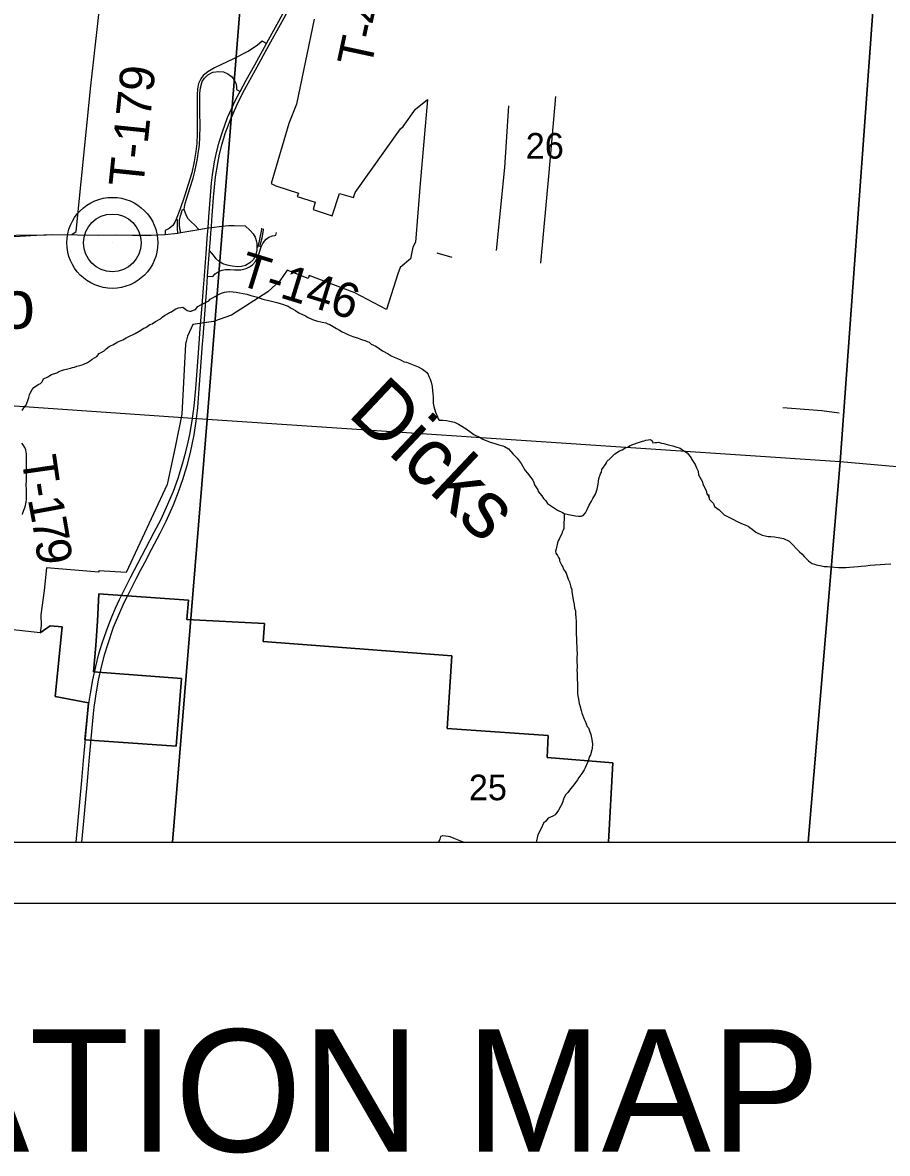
# Model space of a CAD drawing. Extents: x 0 to 34, y 0 to 22.
# Drawn here: x 5.086 to 6.5, y 13.589 to 15.439 of the extents above; entities that cross this region are included whole.
import ezdxf

# ---------------------------------------------------------------- set-up
doc = ezdxf.new("R2010")
doc.units = 0
for name, color, linetype in [('GM_X_City_Street', 7, 'Continuous'), ('GM_X_Corporation', 7, 'Continuous'), ('GM_X_Interchange_Ramps', 7, 'Continuous'), ('GM_X_Minor_River', 7, 'Continuous'), ('GM_X_Minor_River_Text', 7, 'Continuous'), ('GM_X_Rail_Line', 7, 'Continuous'), ('GM_X_Section_Text', 7, 'Continuous'), ('GM_X_State_Route', 7, 'Continuous'), ('GM_X_Township_Road', 7, 'Continuous'), ('GM_X_Township_Road_Text', 7, 'Continuous'), ('GM_X_Unincorporated', 7, 'Continuous'), ('GM_X_Unincorporated_Location', 7, 'Continuous'), ('GM_X_Unincorporated_Text', 7, 'Continuous'), ('SH_Data', 7, 'Continuous'), ('SH_Text', 7, 'Continuous')]:
    doc.layers.add(name, color=color, linetype=linetype)

msp = doc.modelspace()

# ---------------------------------------------------------------- linework, layer by layer
at = {"layer": 'GM_X_City_Street'}
msp.add_line((5.7638, 15.062), (5.7881, 15.055), dxfattribs=at)
for points in [[(5.9336, 15.0452), (5.9473, 15.1933), (5.9583, 15.3179)], [(5.8613, 15.0658), (5.8746, 15.2014), (5.8811, 15.3027)]]:
    msp.add_lwpolyline(points, dxfattribs=at)
at = {"layer": 'GM_X_Corporation'}
for points in [[(2.1, 20.898), (2.1, 14.098), (8.9, 14.098), (8.9, 19.3874)], [(5.5629, 15.4444), (5.5342, 15.3055), (5.5216, 15.2734), (5.4924, 15.1754), (5.5001, 15.1717), (5.5373, 15.1599), (5.5354, 15.1543), (5.5648, 15.1447), (5.5614, 15.1329), (5.5925, 15.1228), (5.6042, 15.1593), (5.6273, 15.1524), (5.63, 15.1609), (5.704, 15.2649), (5.7085, 15.2686), (5.7287, 15.2969), (5.7486, 15.3127), (5.7362, 15.1753), (5.7289, 15.0793), (5.7244, 15.0711), (5.7207, 15.0525), (5.7035, 15.0383), (5.7, 15.0279), (5.6811, 14.9695), (5.6294, 14.9969), (5.555, 15.0252), (5.5534, 15.0203), (5.5189, 15.0335), (5.5066, 15.0163), (5.4871, 14.9982), (5.428, 14.9599), (5.3983, 14.9495), (5.3648, 14.9446), (5.3558, 14.9259), (5.3539, 14.9171), (5.3531, 14.9153), (5.3527, 14.9128), (5.3467, 14.7981), (5.336, 14.7471), (5.3225, 14.6832), (5.2557, 14.5389), (5.2109, 14.5419), (5.211, 14.5395), (5.1255, 14.5467), (5.1215, 14.5095), (5.1158, 14.4697), (5.1168, 14.4526), (5.1151, 14.4405), (5.1314, 14.4521), (5.1509, 14.4503), (5.1394, 14.3361), (5.1941, 14.326), (5.1914, 14.2971), (5.1881, 14.2652), (5.3373, 14.2548), (5.3461, 14.3655), (5.2019, 14.3766), (5.2057, 14.4196), (5.2089, 14.4593), (5.211, 14.5041), (5.3573, 14.4941), (5.3549, 14.4625), (5.4815, 14.4556), (5.4798, 14.4262), (5.7879, 14.4031), (5.7803, 14.2842), (5.9457, 14.2723), (5.944, 14.2365), (6.0516, 14.228), (6.0442, 14.098), (8.9, 14.098)], [(4.8185, 14.098), (5.3312, 14.098), (5.3881, 14.7897), (4.6238, 14.8425)], [(4.828, 14.098), (6.0442, 14.098), (6.0516, 14.228), (5.944, 14.2365), (5.9457, 14.2723), (5.7803, 14.2842), (5.7879, 14.4031), (5.4798, 14.4262), (5.4815, 14.4556), (5.3549, 14.4625), (5.3573, 14.4941), (5.211, 14.5041), (5.2089, 14.4593), (5.2057, 14.4196), (5.2019, 14.3766), (5.3461, 14.3655), (5.3373, 14.2548), (5.1881, 14.2652), (5.1914, 14.2971), (5.1941, 14.326), (5.1394, 14.3361), (5.1509, 14.4503), (5.1314, 14.4521), (5.1151, 14.4405), (4.8868, 14.4655)]]:
    msp.add_lwpolyline(points, dxfattribs=at)
for points in [[(4.4791, 15.9012), (5.4696, 15.8133), (5.3881, 14.7897), (4.6238, 14.8425), (4.6032, 14.8565), (4.5856, 14.8637), (4.5735, 14.8663), (4.5679, 14.8668), (4.5637, 14.865), (4.5556, 14.8606), (4.5464, 14.8574), (4.5354, 14.8542), (4.5274, 14.851), (4.4054, 15.0286)], [(5.4696, 15.8133), (6.4956, 15.7207), (6.423, 14.72), (5.3881, 14.7897)], [(6.4956, 15.7207), (7.5243, 15.6293), (7.4312, 14.6313), (6.423, 14.72)], [(5.3312, 14.098), (6.3708, 14.098), (6.423, 14.72), (5.3881, 14.7897)], [(6.3708, 14.098), (7.3908, 14.098), (7.4312, 14.6313), (6.423, 14.72)]]:
    msp.add_lwpolyline(points, close=True, dxfattribs=at)
at = {"layer": 'GM_X_Interchange_Ramps'}
for points in [[(5.485, 15.4047), (5.4781, 15.4086), (5.4699, 15.4015), (5.4555, 15.3918), (5.4312, 15.3793), (5.3998, 15.3646), (5.3889, 15.3581), (5.3817, 15.3521), (5.3776, 15.3468), (5.3741, 15.3393), (5.3722, 15.3304), (5.3718, 15.3204), (5.3719, 15.2903), (5.3718, 15.2571), (5.371, 15.2408), (5.3694, 15.228), (5.3668, 15.2113), (5.3627, 15.1929), (5.3508, 15.1547), (5.3432, 15.1326), (5.3372, 15.1169), (5.3351, 15.1123), (5.3317, 15.107), (5.326, 15.1021), (5.3195, 15.0985), (5.3193, 15.092)], [(5.3743, 15.1001), (5.3675, 15.1077), (5.3625, 15.1121), (5.3569, 15.1177), (5.3542, 15.1226), (5.3518, 15.1284), (5.3503, 15.1329), (5.351, 15.1371), (5.3522, 15.1428), (5.3542, 15.1496), (5.3602, 15.1687), (5.365, 15.1841), (5.3678, 15.1953), (5.3702, 15.2055), (5.3721, 15.2163), (5.374, 15.2283), (5.3752, 15.2379), (5.3761, 15.2517), (5.3765, 15.2682), (5.3761, 15.2945), (5.3762, 15.3228), (5.3771, 15.3321), (5.38, 15.3421), (5.3837, 15.348), (5.3892, 15.3534), (5.3974, 15.3578), (5.4063, 15.3588), (5.4149, 15.3579), (5.4217, 15.3548), (5.4277, 15.3504), (5.4322, 15.3451), (5.4347, 15.3397), (5.4358, 15.3342), (5.4361, 15.3295), (5.4419, 15.3262)], [(5.3452, 15.0954), (5.3432, 15.1011), (5.3429, 15.1083), (5.3429, 15.1154), (5.3443, 15.1227), (5.3475, 15.1327), (5.3503, 15.1329)], [(5.3372, 15.1169), (5.3388, 15.1164), (5.3391, 15.102), (5.3393, 15.0945)], [(5.3888, 15.0239), (5.3972, 15.0233), (5.4013, 15.0277), (5.4076, 15.032), (5.4128, 15.0338), (5.418, 15.0347), (5.4254, 15.0348), (5.4327, 15.0345), (5.4433, 15.0344), (5.4519, 15.0365), (5.4575, 15.0392), (5.4619, 15.0427), (5.467, 15.048), (5.4706, 15.0542), (5.4731, 15.0616), (5.4761, 15.0719), (5.4788, 15.0772), (5.4811, 15.0808), (5.4845, 15.0843), (5.489, 15.0875), (5.4946, 15.0897), (5.498, 15.0906), (5.5001, 15.091), (5.5016, 15.0955)], [(5.4766, 15.1025), (5.4766, 15.1005), (5.4707, 15.0713), (5.4695, 15.0712)], [(5.4761, 15.0719), (5.4744, 15.0723), (5.4778, 15.0865), (5.4802, 15.0994), (5.4803, 15.1014)]]:
    msp.add_lwpolyline(points, dxfattribs=at)
at = {"layer": 'GM_X_Minor_River'}
for points in [[(5.1601, 14.8723), (5.1643, 14.8732), (5.1678, 14.8743), (5.1708, 14.8753), (5.1747, 14.8767), (5.1797, 14.878), (5.1835, 14.879), (5.1862, 14.88), (5.1924, 14.8829), (5.1971, 14.8857), (5.1999, 14.8879), (5.2077, 14.8926), (5.2116, 14.8974), (5.2144, 14.8992), (5.2198, 14.902), (5.2226, 14.905), (5.2277, 14.9086), (5.2308, 14.9107), (5.2339, 14.9118), (5.2417, 14.9164), (5.2448, 14.9175), (5.2502, 14.9195), (5.2556, 14.9228), (5.263, 14.9267), (5.2657, 14.9277), (5.27, 14.9302), (5.277, 14.9342), (5.2844, 14.9388), (5.2875, 14.9402), (5.2945, 14.9446), (5.298, 14.9459), (5.3034, 14.9496), (5.3116, 14.9542), (5.3144, 14.9568), (5.3183, 14.9593), (5.3233, 14.9625), (5.3264, 14.9643), (5.3299, 14.9657), (5.3342, 14.969), (5.337, 14.9704), (5.3412, 14.9721), (5.3447, 14.9728), (5.3481, 14.973), (5.3525, 14.9698), (5.3551, 14.9678), (5.3589, 14.9665), (5.3616, 14.9668), (5.3658, 14.9682), (5.3689, 14.9696), (5.3725, 14.9744), (5.3776, 14.9769), (5.3873, 14.9819), (5.3907, 14.9833), (5.3931, 14.9862), (5.4009, 14.9905), (5.406, 14.9937), (5.413, 14.9969), (5.4164, 14.9979), (5.4202, 14.9985), (5.4252, 14.9987), (5.4305, 14.9985), (5.4354, 14.9976), (5.4407, 14.9966), (5.4529, 14.9947), (5.4596, 14.9925), (5.4702, 14.9895), (5.4788, 14.9865), (5.4909, 14.9834), (5.5018, 14.9807), (5.5075, 14.9793), (5.5113, 14.978), (5.5173, 14.9759), (5.5203, 14.9747), (5.5255, 14.9718), (5.5322, 14.9677), (5.5378, 14.9637), (5.5486, 14.9588), (5.552, 14.9567), (5.5602, 14.953), (5.567, 14.9509), (5.5761, 14.9486), (5.5821, 14.9473), (5.5851, 14.946), (5.5885, 14.9447), (5.5915, 14.9431), (5.5997, 14.9382), (5.6045, 14.9354), (5.609, 14.9329), (5.6135, 14.9309), (5.6168, 14.9288), (5.6217, 14.9268), (5.6281, 14.9246), (5.6338, 14.9229), (5.639, 14.9208), (5.6473, 14.9182), (5.6499, 14.917), (5.6529, 14.9157), (5.6562, 14.9129), (5.6637, 14.9092), (5.6749, 14.902), (5.6842, 14.8967)], [(5.6842, 14.8967), (5.689, 14.8938), (5.6939, 14.8914), (5.6992, 14.8893), (5.704, 14.8868), (5.7104, 14.8839), (5.7138, 14.883), (5.7224, 14.88), (5.7329, 14.8758), (5.7404, 14.8718), (5.7445, 14.8686), (5.7474, 14.8662), (5.7492, 14.8631), (5.7513, 14.8588), (5.7527, 14.8553), (5.7541, 14.8503), (5.7557, 14.8434), (5.7566, 14.8365), (5.7572, 14.8315), (5.7574, 14.8262), (5.7576, 14.822), (5.7575, 14.819), (5.7578, 14.8163), (5.7587, 14.8109), (5.7614, 14.8017), (5.7628, 14.7978), (5.7646, 14.7944), (5.7652, 14.7913), (5.7674, 14.7885), (5.7735, 14.7883), (5.7796, 14.7877), (5.7845, 14.7868), (5.7924, 14.7849), (5.7991, 14.7817), (5.8017, 14.78), (5.8114, 14.774), (5.82, 14.7679), (5.824, 14.7651), (5.8345, 14.7598), (5.839, 14.757), (5.851, 14.7523), (5.8566, 14.7506), (5.8615, 14.7493), (5.8649, 14.748), (5.8717, 14.7462), (5.8743, 14.745), (5.8807, 14.7417), (5.8883, 14.7327), (5.895, 14.726), (5.9015, 14.7177), (5.9079, 14.7061), (5.912, 14.7017), (5.9207, 14.6904), (5.9224, 14.6865), (5.9234, 14.6827), (5.9288, 14.6745), (5.9295, 14.6714), (5.9353, 14.6643), (5.9382, 14.66), (5.9419, 14.6565), (5.9448, 14.6518), (5.9544, 14.6457), (5.9611, 14.6409), (5.969, 14.6372), (5.972, 14.6356), (5.9788, 14.6342), (5.9818, 14.6333), (5.9905, 14.6319), (5.9954, 14.6313), (5.9996, 14.6315), (6.0031, 14.6325), (6.0067, 14.6366), (6.0095, 14.6422), (6.0128, 14.6493), (6.0165, 14.6556), (6.0186, 14.6601), (6.023, 14.6672), (6.0243, 14.6706), (6.026, 14.6755), (6.0274, 14.6834), (6.028, 14.6879), (6.0285, 14.6929), (6.0315, 14.7008), (6.0327, 14.7034), (6.0333, 14.7075), (6.0405, 14.7175), (6.0414, 14.7206), (6.0473, 14.7257), (6.0501, 14.729), (6.0548, 14.733), (6.0622, 14.7384), (6.0668, 14.7398), (6.0727, 14.7434), (6.0754, 14.7444), (6.0797, 14.7469), (6.0839, 14.7487), (6.0916, 14.7514), (6.1001, 14.7538), (6.1028, 14.7548), (6.1055, 14.7555), (6.1131, 14.7567)], [(5.0852, 14.8042), (5.0884, 14.8083), (5.0912, 14.8124), (5.0933, 14.8161), (5.0949, 14.8206), (5.0963, 14.8255), (5.0972, 14.8297), (5.0984, 14.8327), (5.1017, 14.8386), (5.1045, 14.8416), (5.1084, 14.8445), (5.1127, 14.847), (5.1154, 14.8484), (5.1182, 14.851), (5.1206, 14.8558), (5.1276, 14.8594), (5.1334, 14.863), (5.1419, 14.8657), (5.1454, 14.8678), (5.1528, 14.8706), (5.1601, 14.8723)], [(5.0862, 14.634), (5.0866, 14.6367), (5.0892, 14.6438), (5.0904, 14.6468), (5.0918, 14.654), (5.0924, 14.6585), (5.0928, 14.6703), (5.0923, 14.6764), (5.0921, 14.681), (5.0925, 14.6913), (5.0923, 14.6962), (5.0927, 14.7073), (5.0924, 14.7107), (5.0927, 14.7191), (5.0927, 14.7282), (5.0924, 14.7309), (5.0925, 14.7335), (5.0912, 14.74), (5.0898, 14.7439), (5.0869, 14.7478), (5.0847, 14.7506)], [(6.1131, 14.7567), (6.1157, 14.7544), (6.1171, 14.7513), (6.1206, 14.7519), (6.1236, 14.7518), (6.1263, 14.7521), (6.1312, 14.7507), (6.1346, 14.7502), (6.1403, 14.7485), (6.1444, 14.7476), (6.1493, 14.7466), (6.1542, 14.7449), (6.1617, 14.7424), (6.1658, 14.7392), (6.1729, 14.7351), (6.1798, 14.7265), (6.1805, 14.7238), (6.1863, 14.7156), (6.1884, 14.7106), (6.1908, 14.7051), (6.1917, 14.699), (6.1982, 14.6877), (6.1988, 14.6839), (6.2038, 14.6735), (6.2044, 14.6708), (6.2054, 14.6677), (6.208, 14.6642), (6.209, 14.6615), (6.2091, 14.6641), (6.2077, 14.6668), (6.208, 14.6638), (6.2097, 14.6584), (6.2159, 14.6521), (6.2176, 14.6471), (6.2251, 14.6418), (6.2306, 14.6363), (6.2335, 14.6335), (6.2402, 14.6302), (6.2477, 14.6262), (6.2548, 14.6225), (6.2608, 14.6196), (6.2672, 14.6171), (6.2702, 14.6162), (6.2728, 14.615), (6.2754, 14.613), (6.2791, 14.6102), (6.2854, 14.6054), (6.2959, 14.6004), (6.3053, 14.5981), (6.3099, 14.598), (6.3156, 14.5974), (6.3303, 14.5949), (6.3397, 14.5904), (6.3441, 14.5861), (6.3536, 14.5762), (6.3566, 14.573), (6.3606, 14.5698), (6.3643, 14.5655), (6.3716, 14.5584), (6.3742, 14.556), (6.3772, 14.554), (6.3813, 14.5527), (6.3839, 14.5515), (6.3926, 14.55), (6.3968, 14.5491), (6.4025, 14.5489), (6.4082, 14.5483), (6.4207, 14.5474), (6.4257, 14.5473), (6.4322, 14.5474), (6.4386, 14.5479), (6.4524, 14.5489), (6.4577, 14.5495), (6.465, 14.55), (6.4723, 14.5513), (6.4887, 14.5525), (6.496, 14.553), (6.5059, 14.5534)], [(5.972, 14.6356), (5.9714, 14.6112), (5.9703, 14.6085), (5.9687, 14.6052), (5.9679, 14.6025), (5.9659, 14.5984), (5.9635, 14.5935), (5.9619, 14.5909), (5.9611, 14.5878), (5.9595, 14.5803), (5.9586, 14.5776), (5.9574, 14.5738), (5.9581, 14.5708), (5.9607, 14.5669), (5.9625, 14.5635), (5.964, 14.5608), (5.9643, 14.5581), (5.968, 14.5505), (5.9694, 14.5478), (5.9702, 14.5451), (5.9735, 14.5408), (5.975, 14.5378), (5.9786, 14.5282), (5.9804, 14.524), (5.9829, 14.5152), (5.9843, 14.5114), (5.9846, 14.5083), (5.9856, 14.5011), (5.987, 14.4916), (5.9884, 14.487), (5.989, 14.4809), (5.9901, 14.4767), (5.9904, 14.4733), (5.991, 14.4637), (5.9913, 14.4607), (5.9915, 14.4516), (5.9913, 14.4428), (5.9916, 14.4375), (5.9919, 14.4318), (5.9921, 14.4234), (5.9927, 14.4185), (5.9926, 14.4117), (5.9929, 14.4075), (5.9927, 14.3987), (5.9927, 14.3953), (5.9929, 14.3851), (5.9927, 14.3786), (5.993, 14.3752), (5.9932, 14.3645), (5.9935, 14.3577), (5.9934, 14.3535), (5.9936, 14.3459), (5.9939, 14.341), (5.9942, 14.3375), (5.9952, 14.3318), (5.9962, 14.325), (5.9973, 14.3215), (5.9994, 14.3135), (6.0009, 14.3093), (6.0045, 14.2993), (6.0063, 14.2959), (6.0095, 14.2874), (6.0114, 14.2848), (6.0132, 14.2802), (6.0154, 14.2744), (6.0171, 14.266), (6.0181, 14.2584), (6.0176, 14.2519), (6.0172, 14.2489), (6.0147, 14.241), (6.0135, 14.2384), (6.0111, 14.2312), (6.0099, 14.2285), (6.0063, 14.2195), (6.0044, 14.2165), (6.0008, 14.2101), (5.9958, 14.2038), (5.9938, 14.2), (5.9907, 14.1959), (5.9856, 14.1891), (5.9821, 14.1854), (5.9778, 14.1794), (5.9747, 14.1761), (5.9712, 14.1701), (5.9684, 14.1614), (5.9656, 14.1565), (5.9624, 14.1501), (5.9597, 14.1463), (5.957, 14.143), (5.9531, 14.1404), (5.9497, 14.139), (5.9455, 14.1371), (5.942, 14.1323), (5.9381, 14.1289), (5.9341, 14.1206), (5.9298, 14.112), (5.9282, 14.1078), (5.9265, 14.1003), (5.9259, 14.098)], [(5.8074, 14.098), (5.8031, 14.0997), (5.7948, 14.1029), (5.7922, 14.1041), (5.7854, 14.1069), (5.782, 14.1074), (5.7733, 14.1083), (5.7694, 14.1073), (5.7686, 14.1031), (5.7664, 14.098)]]:
    msp.add_lwpolyline(points, dxfattribs=at)
at = {"layer": 'GM_X_Rail_Line'}
msp.add_lwpolyline([(3.3781, 15.1371), (3.7625, 15.1411), (3.8908, 15.1437), (4.1071, 15.2029), (4.1979, 15.1964), (4.4021, 15.1525), (4.503, 15.1372), (4.7705, 15.1123), (4.89, 15.0915), (4.9836, 15.0897), (5.1669, 15.0922), (5.1739, 15.0968), (5.1979, 15.3351), (5.2386, 15.6999)], dxfattribs=at)
at = {"layer": 'GM_X_State_Route'}
msp.add_line((5.3743, 15.1001), (5.3838, 15.1018), dxfattribs=at)
for points in [[(5.3942, 15.0951), (5.3949, 15.1036), (5.395, 15.1055), (5.3963, 15.1234), (5.3983, 15.1528), (5.4018, 15.1866), (5.4052, 15.2082), (5.408, 15.2234), (5.4127, 15.2406), (5.4174, 15.2571), (5.4255, 15.2787), (5.4366, 15.3038), (5.4465, 15.3236), (5.4699, 15.3663), (5.4896, 15.4021), (5.5109, 15.4407), (5.5311, 15.4782), (5.5438, 15.504), (5.554, 15.5294), (5.5587, 15.5428), (5.5631, 15.5565), (5.5672, 15.5712), (5.5708, 15.5855), (5.5734, 15.5988)], [(5.4419, 15.3262), (5.4519, 15.3448), (5.4658, 15.3698), (5.485, 15.4047), (5.4942, 15.4214), (5.5051, 15.4413), (5.5161, 15.4612), (5.5262, 15.4806), (5.5367, 15.5018), (5.5427, 15.5155), (5.548, 15.529), (5.5531, 15.543), (5.5576, 15.5566), (5.5616, 15.5713), (5.5653, 15.5861), (5.568, 15.5994)], [(5.2156, 14.4219), (5.2205, 14.4363), (5.2258, 14.4499), (5.2322, 14.4667), (5.2379, 14.4807), (5.2444, 14.4949), (5.2506, 14.5071), (5.2633, 14.5319), (5.2754, 14.5552), (5.2878, 14.5791), (5.3016, 14.6052), (5.3126, 14.6266), (5.3238, 14.6507), (5.3328, 14.6724), (5.3408, 14.6937), (5.3478, 14.7168), (5.3532, 14.7364), (5.3571, 14.7526), (5.3596, 14.7648), (5.3637, 14.7873), (5.367, 14.8111), (5.3696, 14.84), (5.3717, 14.8691), (5.3734, 14.8914), (5.3751, 14.9135), (5.3768, 14.9384), (5.3792, 14.9696), (5.382, 15.005), (5.3834, 15.0243), (5.3868, 15.0681), (5.3881, 15.0858), (5.3895, 15.1028), (5.3909, 15.1212), (5.3932, 15.1551), (5.3952, 15.1766), (5.3968, 15.1896), (5.4002, 15.211), (5.4034, 15.226), (5.4077, 15.2431), (5.4129, 15.26), (5.4215, 15.2832), (5.4312, 15.3049), (5.4373, 15.3173), (5.4419, 15.3262)], [(4.8927, 15.1046), (4.9053, 15.1018), (4.9239, 15.0986), (4.9403, 15.0962), (4.9619, 15.0932), (4.9835, 15.0921), (5.0174, 15.0904), (5.0413, 15.0894), (5.0625, 15.0889), (5.0815, 15.0894), (5.1088, 15.0909), (5.1254, 15.0917)], [(5.1254, 15.0917), (5.1357, 15.0921), (5.1762, 15.0914), (5.2104, 15.0912), (5.2373, 15.0917), (5.2659, 15.091), (5.2965, 15.0912), (5.3193, 15.092), (5.3393, 15.0945), (5.3452, 15.0954), (5.3743, 15.1001)], [(5.3838, 15.1018), (5.3895, 15.1028), (5.3949, 15.1036)], [(5.4501, 15.1063), (5.4582, 15.0988), (5.463, 15.0931), (5.4666, 15.0876), (5.4683, 15.0824), (5.4692, 15.0772), (5.4695, 15.0712), (5.469, 15.0664), (5.4681, 15.0618), (5.4659, 15.0554), (5.4632, 15.0508), (5.4578, 15.0457), (5.4509, 15.0415), (5.4444, 15.0397), (5.438, 15.0393), (5.429, 15.0401), (5.4209, 15.0418), (5.4137, 15.0442), (5.4076, 15.0477), (5.4027, 15.0521), (5.3984, 15.0584), (5.3919, 15.0657)], [(5.3919, 15.0657), (5.3934, 15.0847), (5.3942, 15.0951)], [(5.3949, 15.1036), (5.4119, 15.1059), (5.4228, 15.1069), (5.4323, 15.107), (5.4501, 15.1063)], [(5.3813, 14.924), (5.3825, 14.9389), (5.3846, 14.9691), (5.3874, 15.0045), (5.3888, 15.0239), (5.3919, 15.0657)], [(5.372, 14.8044), (5.3726, 14.8093), (5.375, 14.8395), (5.3771, 14.8685), (5.3789, 14.8909), (5.3805, 14.913), (5.3813, 14.924)], [(5.3499, 14.6967), (5.3552, 14.7143), (5.3607, 14.7357), (5.3665, 14.7643), (5.37, 14.7868), (5.372, 14.8044)], [(5.2796, 14.5433), (5.2861, 14.5557), (5.2972, 14.577), (5.3109, 14.6033), (5.3208, 14.6229), (5.3328, 14.6498), (5.3412, 14.6709), (5.3488, 14.6928), (5.3499, 14.6967)], [(5.2048, 14.3293), (5.2064, 14.3408), (5.2104, 14.363), (5.2153, 14.385), (5.2207, 14.406), (5.2254, 14.4215), (5.235, 14.4495), (5.2468, 14.4774), (5.2529, 14.4909), (5.2593, 14.5039), (5.2726, 14.5299), (5.2796, 14.5433)], [(5.1952, 14.3279), (5.197, 14.3413), (5.201, 14.3638), (5.2057, 14.3854), (5.2111, 14.4063), (5.2156, 14.4219)], [(5.1831, 14.1987), (5.1858, 14.2314), (5.189, 14.2671), (5.1919, 14.2967), (5.1941, 14.3193), (5.1952, 14.3279)], [(5.2022, 14.3077), (5.2033, 14.3187), (5.2048, 14.3293)], [(5.1984, 14.2675), (5.2011, 14.2967), (5.2022, 14.3077)], [(5.1922, 14.1978), (5.1951, 14.2303), (5.1983, 14.2665), (5.1984, 14.2675)], [(5.1739, 14.098), (5.1771, 14.1333), (5.1798, 14.1635), (5.1831, 14.1987)], [(5.1831, 14.098), (5.1862, 14.1325), (5.1889, 14.1626), (5.1922, 14.1978)]]:
    msp.add_lwpolyline(points, dxfattribs=at)
at = {"layer": 'GM_X_Township_Road'}
msp.add_lwpolyline([(6.3295, 14.8088), (6.393, 14.8044), (6.4217, 14.8002)], dxfattribs=at)
at = {"layer": 'GM_X_Unincorporated'}
for radius in [0.0744, 0.0472]:
    msp.add_circle((5.233, 15.0784), radius, dxfattribs=at)
at = {"layer": 'GM_X_Unincorporated_Location'}
msp.add_line((5.233, 15.0784), (5.233, 15.0784), dxfattribs=at)
at = {"layer": 'SH_Data'}
for p, q in [((2.1, 14.098), (8.9, 14.098)), ((2, 13.998), (9, 13.998))]:
    msp.add_line(p, q, dxfattribs=at)

# ---------------------------------------------------------------- texts
at = {"layer": 'GM_X_Minor_River_Text'}
msp.add_text('Dicks', height=0.09468, rotation=316.6908, dxfattribs=at).set_placement((5.6159, 14.7969))
at = {"layer": 'GM_X_Section_Text'}
for s, p in [('26', (5.909, 15.2162)), ('25', (5.816, 14.1666))]:
    msp.add_text(s, height=0.04186, rotation=0, dxfattribs=at).set_placement(p)
at = {"layer": 'GM_X_Township_Road_Text'}
for s, height, rotation, p in [('T-430', 0.05682, 77.8661, (5.6558, 15.3633)), ('T-179', 0.05682, 84.0938, (5.2833, 15.1681)), ('T-146', 0.05682, 342.8981, (5.4364, 15.0106)), ('T', 0.0568, 278.1834, (5.0842, 14.7269)), ('-', 0.0568, 279.2855, (5.0905, 14.6837)), ('1', 0.0568, 280.5496, (5.0945, 14.6593)), ('7', 0.0568, 279.8875, (5.1008, 14.6251)), ('9', 0.0568, 276.7545, (5.1067, 14.5914))]:
    msp.add_text(s, height=height, rotation=rotation, dxfattribs=at).set_placement(p)
at = {"layer": 'GM_X_Unincorporated_Text'}
msp.add_text('Excello', height=0.07898, rotation=0, dxfattribs=at).set_placement((4.766, 14.9382))
at = {"layer": 'SH_Text'}
msp.add_text('LOCATION MAP', height=0.2, dxfattribs=at).set_placement((4.3691, 13.5917))

doc.saveas('drawing.dxf')
